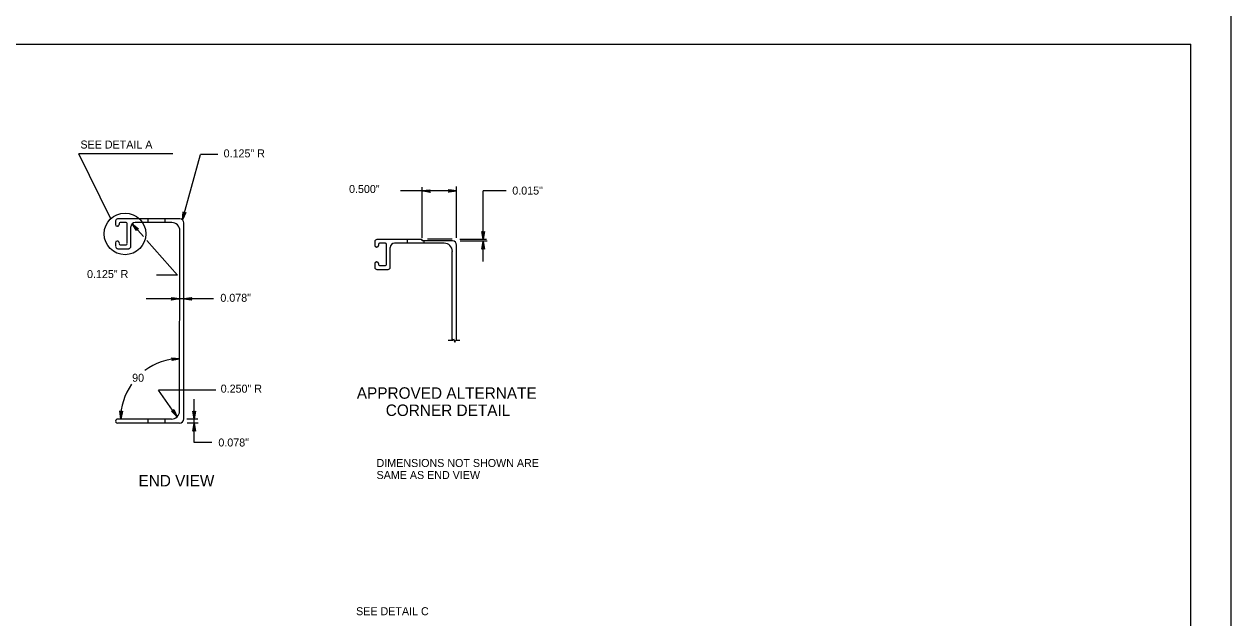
# Model space of a CAD drawing. Extents: x 647822 to 649292, y 298458 to 299646.
# Drawn here: x 648211.1 to 648663.3, y 298821.7 to 299044.1 of the extents above; entities that cross this region are included whole.
import ezdxf

# ---------------------------------------------------------------- set-up
doc = ezdxf.new("R2010")
doc.units = 0
for name, color, linetype in [('1', 7, 'Continuous'), ('2', 7, 'Continuous'), ('3', 7, 'Continuous'), ('XCS-GRID-MIN', 7, 'Continuous')]:
    doc.layers.add(name, color=color, linetype=linetype)

# ---------------------------------------------------------------- blocks, each defined once
blk = doc.blocks.new('RARROW')
at = {"layer": '3'}
blk.add_lwpolyline([(-2.2695, 0.285), (-2.184875, 0.12075), (0, 0), (-2.2695, 0.285), (-2.38575, 0.384625), (0, 0), (-2.183125, -0.108), (-2.262875, -0.2705), (0, 0), (-2.38575, -0.379125), (-2.262875, -0.2705)], dxfattribs=at)

msp = doc.modelspace()

# ---------------------------------------------------------------- linework, layer by layer
at = {"layer": '1'}
for p in [(647862.31, 299036.63), (648648.31, 298472.63)]:
    msp.add_line(p, (648648.31, 299036.63), dxfattribs=at)
at = {"layer": '2'}
for p, q in [((648243.55, 298971.13), (648231.58, 298995.54)), ((648266.76, 298995.54), (648231.58, 298995.54)), ((648270.43, 298970.75), (648277.13, 298995.32)), ((648283.67, 298995.32), (648277.13, 298995.32)), ((648373.15, 298981.61), (648352.06, 298981.61)), ((648360.27, 298964.08), (648360.27, 298982.99)), ((648373.15, 298964.08), (648373.15, 298983.24)), ((648391.67, 298981.61), (648383.15, 298981.61)), ((648383.15, 298963.45), (648383.15, 298981.61)), ((648245.3, 298970.38), (648245.3, 298969)), ((648246.18, 298968.38), (648245.93, 298968.38)), ((648269.43, 298971.13), (648246.18, 298971.13)), ((648246.68, 298969.38), (648246.68, 298969)), ((648249.3, 298969.75), (648247.18, 298969.75)), ((648249.68, 298961.88), (648249.68, 298969.38)), ((648251.05, 298960.88), (648251.05, 298968.13)), ((648255.78, 298964.56), (648251.59, 298969.33)), ((648266.43, 298969.75), (648252.68, 298969.75)), ((648257.43, 298971.13), (648257.43, 298969.75)), ((648263.93, 298969.75), (648263.93, 298971.13)), ((648269.3, 298899.12), (648269.43, 298966.75)), ((648270.93, 298896.23), (648270.93, 298969.63)), ((648245.3, 298962.25), (648245.3, 298960.88)), ((648245.93, 298962.88), (648246.18, 298962.88)), ((648246.68, 298962.25), (648246.68, 298961.88)), ((648268.52, 298950.06), (648257.11, 298963.04)), ((648342.52, 298962.58), (648342.52, 298961.2)), ((648360.27, 298963.45), (648343.27, 298963.45)), ((648354.65, 298963.45), (648354.65, 298962.08)), ((648360.27, 298962.95), (648360.27, 298963.45)), ((648371.65, 298962.95), (648360.27, 298962.95)), ((648361.02, 298962.08), (648361.02, 298962.95)), ((648371.52, 298963.58), (648362.27, 298963.58)), ((648384.4, 298963.45), (648374.4, 298963.45)), ((648384.65, 298962.83), (648374.52, 298962.83)), ((648383.15, 298955.2), (648383.15, 298962.83)), ((648246.18, 298960), (648250.3, 298960)), ((648247.18, 298961.38), (648249.3, 298961.38)), ((648343.27, 298960.58), (648343.15, 298960.58)), ((648343.9, 298961.58), (648343.9, 298961.2)), ((648346.52, 298962.08), (648344.27, 298962.08)), ((648346.9, 298954.08), (648346.9, 298961.58)), ((648348.27, 298953.08), (648348.27, 298960.45)), ((648368.52, 298962.08), (648349.9, 298962.08)), ((648371.52, 298925.7), (648371.52, 298958.95)), ((648373.15, 298925.7), (648373.15, 298961.45)), ((648342.52, 298954.45), (648342.52, 298953.08)), ((648343.15, 298955.08), (648343.27, 298955.08)), ((648343.9, 298954.45), (648343.9, 298954.08)), ((648344.27, 298953.7), (648346.52, 298953.7)), ((648268.52, 298950.06), (648260.69, 298950.06)), ((648343.27, 298952.2), (648347.52, 298952.2)), ((648270.93, 298941.25), (648256.8, 298941.25)), ((648281.99, 298941.25), (648270.93, 298941.25)), ((648370.02, 298925.7), (648371.77, 298925.7)), ((648372.9, 298925.7), (648374.4, 298925.7)), ((648282.92, 298907), (648261.43, 298907)), ((648268.43, 298897), (648261.43, 298907)), ((648274.8, 298894.63), (648274.8, 298903.63)), ((648266.3, 298896.13), (648246.18, 298896.13)), ((648269.33, 298894.63), (648246.18, 298894.63)), ((648257.43, 298896.13), (648257.43, 298894.63)), ((648263.93, 298894.63), (648263.93, 298896.13)), ((648276.18, 298896.13), (648272.05, 298896.13)), ((648276.3, 298894.63), (648272.18, 298894.63)), ((648274.8, 298887.38), (648274.8, 298894.63)), ((648281.43, 298887.38), (648274.8, 298887.38))]:
    msp.add_line(p, q, dxfattribs=at)
msp.add_lwpolyline([(648371.77, 298925.7), (648372.02, 298926.2), (648372.52, 298924.95), (648372.9, 298925.7)], dxfattribs=at)
msp.add_circle((648248.88, 298965.55), 7.8, dxfattribs=at)
for centre, radius, start, end in [((648246.11, 298970.38), 0.795, 90, 180), ((648245.92, 298969), 0.612, 180, 270), ((648246.11, 298969), 0.612, 270, 0), ((648247.12, 298969.39), 0.398, 90, 180), ((648249.31, 298969.39), 0.398, 0, 90), ((648252.68, 298968.13), 1.62, 90, 180), ((648266.43, 298966.75), 3, 359.8939, 90), ((648269.43, 298969.63), 1.5, 0, 90), ((648245.92, 298962.21), 0.612, 90, 180), ((648246.11, 298962.21), 0.612, 0, 90), ((648343.29, 298962.61), 0.795, 90, 180), ((648371.56, 298961.3), 1.6, 0, 90), ((648246.11, 298960.82), 0.795, 180, 270), ((648247.12, 298961.82), 0.398, 180, 270), ((648249.31, 298961.82), 0.398, 270, 0), ((648250.3, 298960.82), 0.795, 270, 0), ((648343.11, 298961.22), 0.612, 180, 270), ((648343.29, 298961.22), 0.612, 270, 0), ((648344.3, 298961.62), 0.398, 90, 180), ((648346.49, 298961.62), 0.398, 0, 90), ((648349.87, 298960.42), 1.59, 90, 180), ((648368.49, 298958.95), 3.08, 0, 90), ((648343.11, 298954.43), 0.612, 90, 180), ((648343.29, 298954.43), 0.612, 0, 90), ((648344.3, 298954.04), 0.398, 180, 270), ((648346.49, 298954.04), 0.398, 270, 0), ((648343.29, 298953.05), 0.795, 180, 270), ((648347.49, 298953.05), 0.795, 270, 0), ((648269.79, 298896.24), 22.55, 91.156, 126.6633), ((648269.79, 298896.24), 22.55, 144.8324, 180.2847), ((648266.3, 298899.13), 3, 270, 359.8939), ((648246.07, 298895.38), 0.758, 81.3591, 278.1482), ((648269.33, 298896.23), 1.6, 270, 0)]:
    msp.add_arc(centre, radius, start, end, dxfattribs=at)
at = {"layer": 'XCS-GRID-MIN'}
msp.add_lwpolyline([(647822.31, 299051.63), (648663.31, 299051.63), (648663.31, 298457.63), (647822.31, 298457.63)], close=True, dxfattribs=at)

# ---------------------------------------------------------------- block references
at = {"layer": '2', "xscale": 1.2574347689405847, "yscale": 1.3092961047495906}
for p, rotation in [((648360.27, 298981.61), 180), ((648270.43, 298970.75), -104.793858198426), ((648251.59, 298969.33), 131.44756539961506), ((648383.15, 298962.83), 89.99999999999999), ((648383.15, 298963.45), -90.00000000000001), ((648270.93, 298941.25), 180), ((648269.34, 298918.78), 4.548170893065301), ((648247.25, 298896.16), -92.99557749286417), ((648268.43, 298897), -55.09389984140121), ((648274.8, 298896.13), -90.00000000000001), ((648274.8, 298894.63), 89.99999999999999)]:
    msp.add_blockref('RARROW', p, dxfattribs=dict(at, rotation=rotation))
for p in [(648373.15, 298981.61), (648269.3, 298941.25)]:
    msp.add_blockref('RARROW', p, dxfattribs=at)

# ---------------------------------------------------------------- texts
at = {"layer": '2'}
for s, height, p in [('SEE DETAIL A', 3, (648232.18, 298997.52)), ('0.125" R', 3, (648285.84, 298994.2)), ('0.500"', 3, (648332.84, 298980.86)), ('0.015"', 3, (648394.02, 298980.26)), ('0.125" R', 3, (648234.65, 298948.99)), ('0.078"', 3, (648284.62, 298940.09)), ('90', 3, (648251.55, 298910.13)), ('0.250" R', 3, (648284.74, 298906.05)), ('APPROVED ALTERNATE', 4.3, (648335.75, 298903.76)), ('CORNER DETAIL', 4.3, (648346.6, 298897.31)), ('0.078"', 3, (648283.87, 298885.88)), ('DIMENSIONS NOT SHOWN ARE', 3, (648343.15, 298878.2)), ('SAME AS END VIEW', 3, (648343.15, 298873.7)), ('END VIEW', 4.3, (648253.93, 298870.92)), ('SEE DETAIL C', 3, (648335.49, 298822.66))]:
    msp.add_text(s, height=height, dxfattribs=at).set_placement(p)

doc.saveas('drawing.dxf')
